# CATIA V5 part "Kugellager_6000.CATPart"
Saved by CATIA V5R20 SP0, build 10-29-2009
Part number: Kugellager_6000
Bounding box of the stored display mesh (mm): x -12.999 to 12.999, y -12.999 to 12.999, z -4 to 4
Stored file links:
  C:\Users\Andi\Desktop\Offene Projekte\Plasmacutter\Z-Achse\Kugellager_6000.CATPart
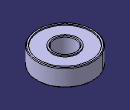
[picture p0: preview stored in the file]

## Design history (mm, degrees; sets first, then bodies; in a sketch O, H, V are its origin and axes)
AxisSystem1: origin (0, 0, 0), X (1, 0, 0), Y (0, 1, 0), Z (0, 0, 1)
Body1 (main body)
  Sketch1 on YZ plane of AxisSystem1, origin (0, 0, 0), H (0, 1, 0), V (0, 0, 1)
    line L1 (5, -4) -> (5, 4)
    line L2 (5, 4) -> (6, 4)
    line L3 (6, 4) -> (6, 3.5)
    line L4 (6, 3.5) -> (12, 3.5)
    line L5 (12, 3.5) -> (12, 4)
    point P6 (12, 4)
    line L6 (12, 4) -> (13, 4)
    line L7 (13, 4) -> (13, -4)
    line L8 (13, -4) -> (12, -4)
    point P9 (12, -4)
    line L9 (12, -4) -> (12, -3.5)
    line L10 (12, -3.5) -> (6, -3.5)
    point P11 (6, -3.5)
    line L11 (6, -3.5) -> (6, -4)
    point P12 (6, -4)
    line L12 (6, -4) -> (5, -4)
    reference projected line E1 through (0, 0) direction (0, 1) from edge [ZX plane of AxisSystem1 | YZ plane of AxisSystem1]
    construction line L13 (9, 3.5) -> (9, -3.5)
    point P13 (9, 3.5)
    point P14 (9, -3.5)
    distance L1 V = 5
    distance L7 E1 = 13
    length L7 = 8
    distance L4 L6 = 0.5
    distance L3 L1 = 1
    vertical: L1 V, L3 V, L5 V, L7 V, L9 V, L11 V, L13 V
    horizontal: L2 H, L4 H, L6 H, L8 H, L10 H, L12 H
    coincidence: P6 L2, P9 L5, P11 L3, P12 L8
    symmetry: L8 L6 H, L10 L4 H, L3 L5 L13, L1 L7 L13
    midpoint: P13 L4, P14 L10
  Shaft1: profile Sketch1, axis Sketch1.V, angle 360
  Chamfer1: length 0.3, angle 45, on edge [face of Shaft1 from Sketch1.L7 | face of Shaft1 from Sketch1.L6]; edge [face of Shaft1 from Sketch1.L8 | face of Shaft1 from Sketch1.L7]; edge [face of Shaft1 from Sketch1.L2 | face of Shaft1 from Sketch1.L1]; edge [face of Shaft1 from Sketch1.L1 | face of Shaft1 from Sketch1.L12]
